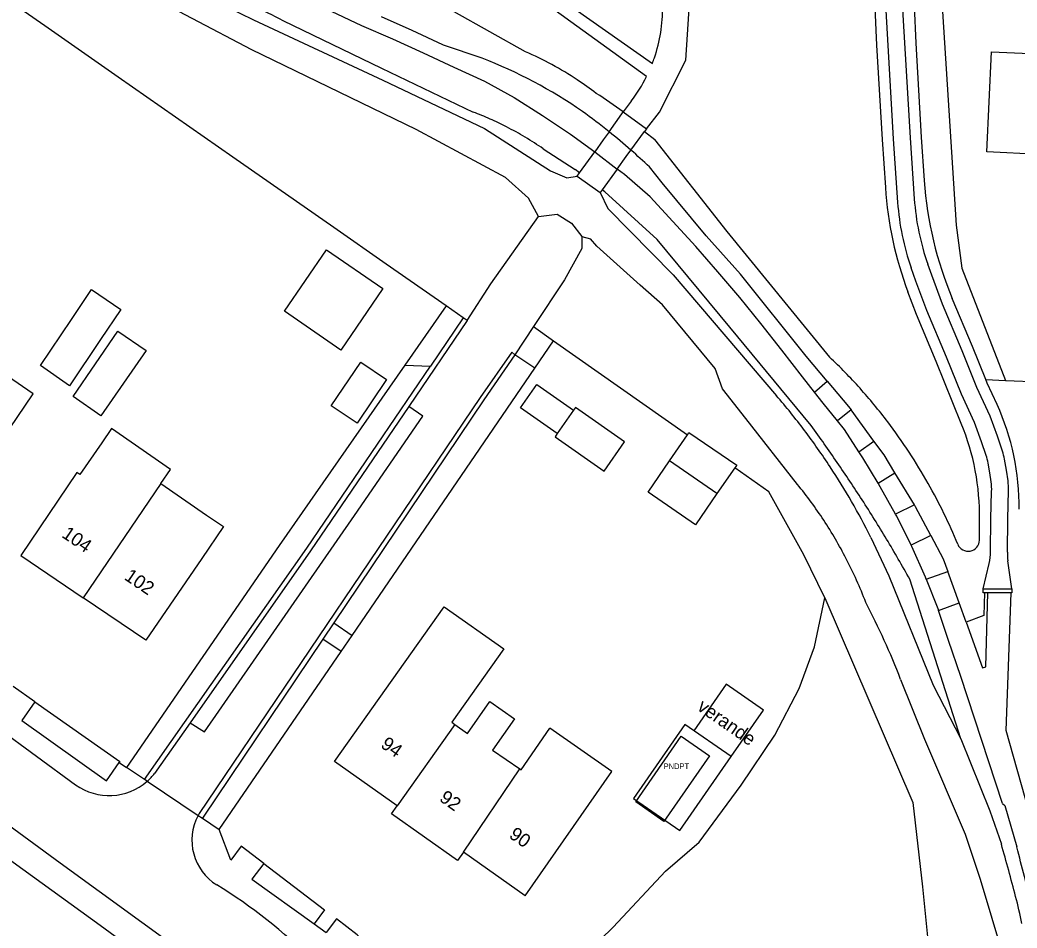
# Model space of a CAD drawing. Extents: x 194485 to 197793, y 468269 to 470822.
# Drawn here: x 194697.5 to 194786.2, y 470533.9 to 470614.7 of the extents above; entities that cross this region are included whole.
import ezdxf

# ---------------------------------------------------------------- set-up
doc = ezdxf.new("R2010")
doc.units = 0
for name, color, linetype in [('BAG plantopografie panden grensvlak pand', 7, 'Continuous'), ('BAG plantopografie panden kenmerkpunt', 7, 'Continuous'), ('BAG plantopografie panden lijnelement overig', 7, 'Continuous'), ('BAG plantopografie panden tekst opmerking', 7, 'Continuous'), ('BGT grensvlak begroeid terreindeel', 7, 'Continuous'), ('BGT grensvlak begroeid terreindeel LR', 7, 'Continuous'), ('BGT grensvlak gebouwinstallatie plus 1', 7, 'Continuous'), ('BGT grensvlak onbegroeid terreindeel', 7, 'Continuous'), ('BGT grensvlak overbruggingsdeel plus 1', 7, 'Continuous'), ('BGT grensvlak pand op maaiveld', 7, 'Continuous'), ('BGT grensvlak pand op maaiveld LR', 7, 'Continuous'), ('BGT grensvlak scheiding', 7, 'Continuous'), ('BGT grensvlak waterdeel', 7, 'Continuous'), ('BGT grensvlak waterdeel LR', 7, 'Continuous'), ('BGT grensvlak wegdeel', 7, 'Continuous'), ('BGT lijnelement kunstwerkdeel stuw', 7, 'Continuous'), ('BGT lijnelement scheiding muur', 7, 'Continuous'), ('BGT tekst huisnummerreeks', 7, 'Continuous')]:
    doc.layers.add(name, color=color, linetype=linetype)

msp = doc.modelspace()

# ---------------------------------------------------------------- linework, layer by layer
at = {"layer": 'BAG plantopografie panden grensvlak pand'}
msp.add_lwpolyline([(194752.065, 470545.461), (194756.171, 470542.607), (194760.737, 470549.175), (194756.632, 470552.029), (194752.065, 470545.461)], dxfattribs=at)
at = {"layer": 'BAG plantopografie panden lijnelement overig'}
msp.add_lwpolyline([(194760.737, 470549.175), (194763.612, 470553.31), (194760.301, 470555.612), (194757.426, 470551.477)], dxfattribs=at)
at = {"layer": 'BGT grensvlak begroeid terreindeel'}
for p, q in [((194742.438, 470611.896), (194736.092, 470615.433)), ((194720.86, 470614.685), (194729.643, 470610.445)), ((194729.643, 470610.445), (194737.801, 470606.529)), ((194753.042, 470604.808), (194753.965, 470604.1)), ((194760.396, 470595.903), (194753.965, 470604.1)), ((194744.031, 470603.254), (194746.881, 470601.409)), ((194747.255, 470601.126), (194746.881, 470601.409)), ((194769.505, 470584.721), (194760.396, 470595.903)), ((194782.823, 470568.438), (194782.843, 470570.264)), ((194781.174, 470550.752), (194776.631, 470564.964))]:
    msp.add_line(p, q, dxfattribs=at)
for points in [[(194774.519, 470729.54), (194774.391, 470727.444), (194774.132, 470719.837), (194773.85, 470711.578), (194773.603, 470699.425), (194773.182, 470668.703), (194773.16, 470658.53), (194772.991, 470642.155), (194773.372, 470619.216), (194773.675, 470612.487)], [(194773.675, 470612.487), (194774.165, 470604.078), (194774.457, 470599.806)], [(194767.858, 470578.625), (194760.617, 470587.39), (194754.175, 470595.195), (194749.493, 470599.43), (194749.273, 470599.597)], [(194781.216, 470578.815), (194778.969, 470584.326), (194777.217, 470588.501), (194776.458, 470590.539)], [(194784.39, 470580.515), (194783.528, 470582.416), (194783.402, 470582.723)]]:
    msp.add_lwpolyline(points, dxfattribs=at)
for centre, radius, start, end in [((194770.667, 470714.262), 111.339, 240.32776, 243.4265), ((194730.879, 470585.111), 29.173, 61.50184, 66.65708), ((194730.387, 470584.149), 30.253, 56.58034, 61.55205), ((194730.069, 470583.746), 30.764, 52.62267, 56.50035), ((194725.566, 470572.065), 42.924, 53.41945, 57.31686), ((194727.555, 470579.555), 28.854, 65.9769, 69.2014), ((194727.292, 470578.985), 29.482, 62.80403, 65.95977), ((194727.185, 470578.791), 29.703, 59.12109, 62.7931), ((194727.454, 470579.247), 29.175, 55.37521, 59.11456), ((194807.396, 470602.069), 33.017, 183.93013, 200.4392), ((194736.685, 470550.065), 47.73, 41.9122, 46.55944), ((194737.205, 470550.538), 47.028, 37.18971, 41.9058), ((194764.352, 470571.425), 22.004, 359.3671, 24.40032), ((194659.901, 470499.662), 133.753, 34.46689, 36.18277), ((194736.802, 470550.237), 47.531, 33.2217, 37.185), ((194760.855, 470570.511), 21.989, 359.35714, 22.18867), ((194737.787, 470550.858), 46.367, 29.18285, 33.24673), ((194661.782, 470500.886), 131.509, 32.74596, 34.49137), ((194739.869, 470551.41), 44.283, 22.10416, 29.8728), ((194655.624, 470496.985), 138.799, 31.02582, 32.7253), ((194660.672, 470500.099), 132.868, 29.22157, 30.99674), ((194781.823, 470568.449), 1, 202.10262, 359.35933)]:
    msp.add_arc(centre, radius, start, end, dxfattribs=at)
at = {"layer": 'BGT grensvlak begroeid terreindeel LR'}
msp.add_lwpolyline([(194769.071, 470563.309), (194776.9, 470545.1), (194777.75, 470537.6), (194779, 470525.15), (194779.193, 470512.957)], dxfattribs=at)
at = {"layer": 'BGT grensvlak gebouwinstallatie plus 1'}
for points in [[(194725.171, 470580.391), (194727.801, 470584.288), (194730.1, 470582.736), (194727.47, 470578.839), (194725.171, 470580.391)], [(194745.28, 470577.921), (194741.999, 470580.215), (194743.451, 470582.293), (194746.733, 470579.998)], [(194759.473, 470572.602), (194757.563, 470569.815), (194753.354, 470572.699), (194755.264, 470575.486)]]:
    msp.add_lwpolyline(points, dxfattribs=at)
at = {"layer": 'BGT grensvlak onbegroeid terreindeel'}
for p, q in [((194744.937, 470586.172), (194756.853, 470577.816)), ((194783.402, 470582.723), (194785.14, 470582.646)), ((194785.14, 470582.646), (194808.41, 470581.622)), ((194715.213, 470542.69), (194726.046, 470558.537))]:
    msp.add_line(p, q, dxfattribs=at)
for points in [[(194779.182, 470744.83), (194778.422, 470736.048), (194777.887, 470727.278), (194777.63, 470719.718), (194777.349, 470711.483), (194777.102, 470699.366), (194776.682, 470668.676), (194776.66, 470658.508), (194776.491, 470642.166), (194776.871, 470619.323), (194777.171, 470612.654)], [(194735.382, 470589.272), (194730.058, 470592.989), (194725.394, 470596.246), (194716.413, 470602.517), (194706.217, 470609.637), (194699.697, 470614.19), (194693.091, 470618.802), (194684.78, 470624.865), (194676.675, 470630.888)], [(194779.404, 470617.811), (194780.746, 470596.469), (194781.255, 470592.647), (194785.14, 470582.646)], [(194777.171, 470612.654), (194777.658, 470604.3), (194777.922, 470600.436)], [(194783.402, 470582.723), (194782.203, 470585.663), (194780.415, 470589.926)], [(194731.72, 470584.018), (194720.531, 470567.962), (194706.969, 470548.216)], [(194727.024, 470559.968), (194741.226, 470580.743), (194743.266, 470583.727)], [(194769.071, 470563.309), (194767.214, 470567.138), (194764.106, 470572.729), (194761.066, 470574.861)], [(194739.471, 470520.723), (194745.69, 470529.554), (194750.244, 470534.006), (194754.901, 470538.976), (194757.903, 470541.564), (194761.629, 470546.638), (194764.63, 470551.09), (194766.804, 470555.231), (194768.149, 470558.959), (194769.071, 470563.309)], [(194698.811, 470554.05), (194706.372, 470548.731), (194706.319, 470548.656)], [(194719.183, 470539.657), (194724.578, 470535.534), (194723.658, 470534.305)], [(194733.74, 470527.297), (194733.278, 470527.827), (194727.472, 470533.322), (194725.628, 470534.731), (194724.725, 470533.544)]]:
    msp.add_lwpolyline(points, dxfattribs=at)
msp.add_arc((194810.87, 470602.701), 33.026, 183.93213, 202.75606, dxfattribs=at)
at = {"layer": 'BGT grensvlak overbruggingsdeel plus 1'}
for p, q in [((194751.147, 470606.534), (194753.204, 470605.032)), ((194749.881, 470604.775), (194749.368, 470604.062)), ((194751.833, 470603.137), (194753.042, 470604.808)), ((194753.204, 470605.032), (194753.042, 470604.808)), ((194749.368, 470604.062), (194748.603, 470602.999)), ((194747.255, 470601.126), (194748.603, 470602.999)), ((194750.617, 470601.455), (194751.418, 470602.563)), ((194751.418, 470602.563), (194751.833, 470603.137)), ((194747.043, 470600.832), (194747.255, 470601.126)), ((194747.043, 470600.832), (194749.105, 470599.364)), ((194750.617, 470601.455), (194749.273, 470599.597)), ((194749.273, 470599.597), (194749.105, 470599.364))]:
    msp.add_line(p, q, dxfattribs=at)
msp.add_lwpolyline([(194749.881, 470604.775), (194751.02, 470606.358), (194751.147, 470606.534)], dxfattribs=at)
at = {"layer": 'BGT grensvlak pand op maaiveld'}
for p, q in [((194783.484, 470602.975), (194783.89, 470611.899)), ((194792.365, 470602.548), (194783.484, 470602.975)), ((194699.321, 470583.983), (194702.058, 470588.074)), ((194704.659, 470586.283), (194701.874, 470582.174)), ((194701.874, 470582.174), (194699.321, 470583.983)), ((194746.733, 470579.998), (194745.28, 470577.921)), ((194755.264, 470575.486), (194756.853, 470577.816)), ((194759.473, 470572.602), (194755.264, 470575.486)), ((194761.066, 470574.861), (194759.473, 470572.602)), ((194710.014, 470573.482), (194714.083, 470570.67)), ((194735.89, 470552.23), (194736.167, 470552.034)), ((194742.064, 470548.015), (194744.609, 470551.699)), ((194750.13, 470547.86), (194744.609, 470551.699)), ((194739.502, 470549.762), (194741.932, 470548.105)), ((194741.932, 470548.105), (194742.064, 470548.015)), ((194742.433, 470536.793), (194750.13, 470547.86)), ((194736.921, 470540.672), (194736.401, 470539.936)), ((194742.433, 470536.793), (194736.921, 470540.672))]:
    msp.add_line(p, q, dxfattribs=at)
for points in [[(194783.89, 470611.899), (194788.671, 470611.669), (194788.718, 470612.657), (194792.816, 470612.463), (194792.365, 470602.548)], [(194726.023, 470585.344), (194721.011, 470588.826), (194724.752, 470594.269), (194729.751, 470590.826), (194726.023, 470585.344)], [(194702.058, 470588.074), (194703.837, 470590.744), (194706.453, 470588.946), (194704.659, 470586.283)], [(194704.69, 470579.497), (194702.216, 470581.225), (194706.198, 470587.039), (194708.71, 470585.298), (194704.69, 470579.497)], [(194696.546, 470578.353), (194698.666, 470581.461), (194692.261, 470585.835), (194690.119, 470582.698)], [(194745.28, 470577.921), (194745.084, 470577.64), (194749.451, 470574.587), (194751.261, 470577.176), (194746.894, 470580.229), (194746.733, 470579.998)], [(194710.014, 470573.482), (194710.88, 470574.736), (194705.626, 470578.366), (194704.76, 470577.112)], [(194756.853, 470577.816), (194756.989, 470578.016), (194761.248, 470575.119), (194761.066, 470574.861)], [(194704.76, 470577.112), (194702.807, 470574.275), (194702.552, 470574.453), (194697.556, 470567.068), (194703.116, 470563.301)], [(194714.083, 470570.67), (194715.578, 470569.662), (194713.66, 470566.817)], [(194713.66, 470566.817), (194708.677, 470559.534), (194703.116, 470563.301)], [(194730.584, 470555.986), (194735.207, 470562.516), (194740.512, 470558.76), (194735.89, 470552.23)], [(194731.044, 470544.798), (194725.461, 470548.75), (194730.584, 470555.986)], [(194736.167, 470552.034), (194737.29, 470551.23), (194739.268, 470554.079), (194741.475, 470552.542), (194739.502, 470549.762)], [(194754.751, 470543.419), (194752.264, 470545.147), (194756.284, 470551), (194758.822, 470549.234), (194754.751, 470543.419)], [(194736.401, 470539.936), (194730.537, 470544.082), (194731.044, 470544.798)]]:
    msp.add_lwpolyline(points, dxfattribs=at)
at = {"layer": 'BGT grensvlak pand op maaiveld LR'}
for p, q in [((194710.014, 470573.482), (194703.116, 470563.301)), ((194736.167, 470552.034), (194731.044, 470544.798)), ((194736.921, 470540.672), (194741.932, 470548.105))]:
    msp.add_line(p, q, dxfattribs=at)
at = {"layer": 'BGT grensvlak scheiding'}
for p, q in [((194783.164, 470564.096), (194785.713, 470564.096)), ((194783.581, 470563.741), (194783.285, 470563.741)), ((194785.651, 470563.741), (194783.581, 470563.741))]:
    msp.add_line(p, q, dxfattribs=at)
for points in [[(194783.285, 470563.741), (194783.218, 470561.73), (194781.632, 470561.143)], [(194781.632, 470561.143), (194783.105, 470557.091), (194783.388, 470557.177), (194783.581, 470563.741)], [(194783.285, 470563.741), (194783.164, 470563.741), (194783.164, 470564.096)], [(194785.713, 470564.096), (194785.713, 470563.741), (194785.651, 470563.741)]]:
    msp.add_lwpolyline(points, dxfattribs=at)
at = {"layer": 'BGT grensvlak waterdeel'}
for p, q in [((194748.603, 470602.999), (194750.617, 470601.455)), ((194773.435, 470577.259), (194771.409, 470580.034)), ((194777.046, 470571.58), (194775.311, 470574.427)), ((194783.164, 470564.096), (194783.685, 470566.359)), ((194785.713, 470564.096), (194785.36, 470566.607)), ((194781.016, 470562.848), (194780.004, 470565.65)), ((194781.632, 470561.143), (194781.016, 470562.848)), ((194784.886, 470545.005), (194781.163, 470556.316))]:
    msp.add_line(p, q, dxfattribs=at)
for points in [[(194774.434, 470616.638), (194775.163, 470604.142), (194775.55, 470598.492)], [(194775.934, 470616.694), (194776.66, 470604.237), (194777.032, 470598.798)], [(194725.154, 470615.501), (194727.875, 470614.238), (194730.628, 470613.045), (194733.353, 470611.79), (194736.076, 470610.532), (194738.794, 470609.263), (194741.428, 470607.826), (194743.962, 470606.221), (194746.458, 470604.556), (194748.603, 470602.999)], [(194738.589, 470611.326), (194735.161, 470612.474), (194735.083, 470612.51), (194732.365, 470613.781), (194729.629, 470615.011)], [(194769.285, 470582.58), (194767.402, 470584.8), (194761.588, 470592.118), (194758.505, 470595.505), (194754.615, 470600.238), (194753.477, 470601.647)], [(194768.147, 470581.615), (194767.076, 470582.966), (194765.261, 470585.355), (194763.394, 470587.703), (194761.501, 470590.03), (194759.566, 470592.323), (194757.59, 470594.58), (194755.565, 470596.794), (194753.527, 470598.995), (194751.258, 470600.958), (194750.617, 470601.455)], [(194783.419, 470575.983), (194783.018, 470577.187), (194782.38, 470578.894), (194781.231, 470581.427), (194779.893, 470584.708), (194778.147, 470588.87), (194777.169, 470591.493), (194776.752, 470592.676)], [(194784.876, 470576.355), (194784.432, 470577.686), (194783.767, 470579.467), (194782.609, 470582.02), (194781.279, 470585.281), (194779.542, 470589.422), (194778.579, 470592.005), (194778.234, 470592.982)], [(194769.285, 470582.58), (194771.19, 470580.334), (194771.409, 470580.034)], [(194770.195, 470579.056), (194768.94, 470580.615), (194768.147, 470581.615)], [(194772.101, 470576.284), (194770.821, 470578.279), (194770.195, 470579.056)], [(194775.311, 470574.427), (194774.341, 470576.018), (194773.435, 470577.259)], [(194773.814, 470573.515), (194772.441, 470575.753), (194772.101, 470576.284)], [(194783.866, 470573.621), (194783.752, 470574.418), (194783.596, 470575.286)], [(194785.369, 470573.706), (194785.234, 470574.656), (194785.054, 470575.658)], [(194775.373, 470570.748), (194774.01, 470573.196), (194773.814, 470573.515)], [(194783.812, 470567.425), (194783.844, 470570.322), (194783.914, 470572.771)], [(194785.311, 470567.36), (194785.344, 470570.292), (194785.417, 470572.856)], [(194778.494, 470568.866), (194777.154, 470571.403), (194777.046, 470571.58)], [(194776.749, 470567.999), (194775.469, 470570.575), (194775.373, 470570.748)], [(194778.494, 470568.866), (194779.593, 470566.787), (194780.004, 470565.65)], [(194778.102, 470564.963), (194778.03, 470565.15), (194776.804, 470567.888), (194776.749, 470567.999)], [(194778.102, 470564.963), (194779.114, 470562.353), (194779.172, 470562.181)], [(194789.323, 470536.717), (194788.507, 470539.638), (194787.209, 470544.355), (194785.191, 470551.513), (194785.651, 470563.741)], [(194781.163, 470556.316), (194780.078, 470559.512), (194779.172, 470562.181)], [(194784.886, 470545.005), (194785.096, 470544.839), (194786.148, 470541.14)]]:
    msp.add_lwpolyline(points, dxfattribs=at)
for centre, radius, start, end in [((194722.498, 470570.231), 44.133, 55.4562, 68.61674), ((194710.988, 470556.492), 61.999, 51.14765, 53.89387), ((194710.878, 470556.314), 62.207, 48.82507, 51.17226), ((194711.443, 470556.921), 61.378, 46.77752, 48.84881), ((194797.488, 470599.994), 21.989, 183.91593, 199.43805), ((194799.035, 470600.313), 22.055, 183.93925, 199.41473), ((194778.686, 470574.41), 4.988, 10.11488, 18.38273), ((194780.052, 470574.752), 5.084, 10.26872, 18.38329), ((194778.913, 470572.915), 5.003, 358.35155, 8.11264), ((194780.416, 470573), 5.003, 358.35155, 8.11264), ((194778.791, 470567.483), 5.021, 347.06926, 359.3427), ((194790.248, 470567.303), 4.937, 179.34048, 188.10584), ((194546.797, 470478.218), 247.483, 13.46575, 14.72899)]:
    msp.add_arc(centre, radius, start, end, dxfattribs=at)
at = {"layer": 'BGT grensvlak waterdeel LR'}
for p, q in [((194768.147, 470581.615), (194769.285, 470582.58)), ((194771.409, 470580.034), (194770.195, 470579.056)), ((194772.101, 470576.284), (194773.435, 470577.259)), ((194773.814, 470573.515), (194775.311, 470574.427)), ((194777.046, 470571.58), (194775.373, 470570.748)), ((194778.494, 470568.866), (194776.749, 470567.999)), ((194778.102, 470564.963), (194780.004, 470565.65)), ((194779.172, 470562.181), (194781.016, 470562.848))]:
    msp.add_line(p, q, dxfattribs=at)
at = {"layer": 'BGT grensvlak wegdeel'}
for p, q in [((194737.372, 470622.383), (194753.732, 470610.859)), ((194753.216, 470609.687), (194736.912, 470621.494)), ((194751.853, 470607.5), (194751.147, 470606.534)), ((194747.456, 470595.447), (194748.218, 470595.24)), ((194735.382, 470589.272), (194731.72, 470584.018)), ((194736.907, 470588.206), (194735.382, 470589.272)), ((194737.248, 470587.967), (194732.065, 470580.333)), ((194736.907, 470588.206), (194734.002, 470583.927)), ((194737.248, 470587.967), (194736.907, 470588.206)), ((194743.173, 470587.441), (194741.515, 470584.924)), ((194743.173, 470587.441), (194744.937, 470586.172)), ((194741.515, 470584.924), (194738.733, 470580.924)), ((194743.266, 470583.727), (194741.515, 470584.924)), ((194731.72, 470584.018), (194734.002, 470583.927)), ((194738.733, 470580.924), (194725.395, 470561.082)), ((194725.395, 470561.082), (194724.428, 470559.643)), ((194725.395, 470561.082), (194727.024, 470559.968)), ((194726.046, 470558.537), (194727.024, 470559.968)), ((194726.046, 470558.537), (194724.428, 470559.643)), ((194698.811, 470554.05), (194696.889, 470555.403)), ((194692.056, 470554.269), (194702.437, 470546.679)), ((194698.811, 470554.05), (194697.662, 470552.384)), ((194697.662, 470552.384), (194705.184, 470547.031)), ((194712.626, 470552.199), (194709.46, 470547.684)), ((194701.055, 470539.687), (194688.113, 470549.192)), ((194705.184, 470547.031), (194706.319, 470548.656)), ((194706.319, 470548.656), (194706.969, 470548.216)), ((194708.566, 470547.134), (194706.969, 470548.216)), ((194708.793, 470546.981), (194708.566, 470547.134)), ((194708.793, 470546.981), (194713.336, 470543.944)), ((194713.336, 470543.944), (194713.71, 470543.694)), ((194713.71, 470543.694), (194715.213, 470542.69)), ((194712.769, 470531.198), (194701.055, 470539.687)), ((194723.658, 470534.305), (194724.725, 470533.544))]:
    msp.add_line(p, q, dxfattribs=at)
for points in [[(194743.606, 470597.23), (194742.708, 470598.874), (194740.675, 470600.692), (194732.734, 470604.967), (194718.113, 470612.063), (194707.503, 470617.66)], [(194753.204, 470605.032), (194754.361, 470606.531), (194756.722, 470611.134), (194757.073, 470616.663)], [(194718.26, 470614.724), (194729.755, 470609.361), (194738.809, 470605.065), (194744.667, 470601.292), (194746.128, 470600.676), (194747.043, 470600.832)], [(194749.105, 470599.364), (194749.785, 470597.944), (194755.579, 470592.036), (194764.776, 470581.293)], [(194737.248, 470587.967), (194739.358, 470591.249), (194743.606, 470597.23)], [(194743.606, 470597.23), (194745.273, 470597.439), (194746.555, 470596.652), (194747.456, 470595.447)], [(194747.456, 470595.447), (194747.454, 470594.387), (194745.92, 470591.613), (194743.173, 470587.441)], [(194766.643, 470573.394), (194762.062, 470579.252), (194759.964, 470581.9), (194759.312, 470583.718), (194754.626, 470589.381), (194752.66, 470591.14), (194748.799, 470594.608), (194748.218, 470595.24)], [(194743.266, 470583.727), (194743.279, 470583.747), (194744.937, 470586.172)], [(194741.515, 470584.924), (194741.23, 470585.15), (194738.411, 470581.14)], [(194708.566, 470547.134), (194722.994, 470567.711), (194734.002, 470583.927)], [(194738.411, 470581.14), (194713.43, 470544.111), (194713.336, 470543.944)], [(194712.626, 470552.199), (194713.888, 470551.377), (194727.225, 470570.639), (194733.33, 470579.457), (194732.065, 470580.333)], [(194732.065, 470580.333), (194723.339, 470567.478), (194712.626, 470552.199)], [(194773.178, 470568.686), (194774.762, 470565.254), (194778.702, 470555.537), (194781.174, 470550.752)], [(194724.428, 470559.643), (194713.778, 470543.8), (194713.71, 470543.694)], [(194775.818, 470556.047), (194777.936, 470550.742), (194781.571, 470542.269), (194782.878, 470538.288), (194784.957, 470531.327)], [(194781.174, 470550.752), (194783.747, 470544.341), (194784.777, 470541.377)], [(194726.856, 470506.908), (194725.926, 470510.681), (194724.606, 470514.488), (194722.368, 470518.679), (194720.579, 470520.944), (194717.885, 470524.062), (194715.614, 470526.084), (194704.608, 470534.155), (194684.263, 470548.857)], [(194719.183, 470539.657), (194717.156, 470541.206), (194716.226, 470539.966), (194715.213, 470542.69)], [(194719.183, 470539.657), (194718.1, 470538.273), (194723.658, 470534.305)]]:
    msp.add_lwpolyline(points, dxfattribs=at)
for centre, radius, start, end in [((194760.879, 470701.076), 96.297, 239.39564, 243.73118), ((194741.028, 470615.774), 13.621, 350.81545, 0.55063), ((194741.149, 470615.735), 13.495, 341.06791, 350.89567), ((194742.111, 470615.388), 12.473, 338.70665, 341.14249), ((194740.931, 470615.825), 13.733, 322.68422, 333.45114), ((194717.078, 470540.369), 62.848, 37.01123, 40.62866), ((194717.087, 470540.405), 62.819, 33.37038, 36.98985), ((194717.78, 470540.851), 61.995, 30.02849, 33.37912), ((194737.645, 470549.657), 37.475, 33.25422, 39.30331), ((194717.124, 470540.443), 62.768, 26.74122, 30.05083), ((194737.678, 470549.637), 37.458, 27.25458, 33.30627), ((194736.982, 470549.281), 38.239, 20.85585, 27.25185), ((194713.712, 470532.041), 66.584, 21.13327, 27.60578), ((194705.373, 470550.894), 5.197, 311.15525, 321.85523), ((194705.424, 470550.847), 5.128, 234.37413, 311.0665), ((194717.44, 470541.73), 4.663, 151.65641, 238.34826), ((194597.725, 470487.719), 194.596, 14.58758, 16.0061), ((194691.304, 470498.999), 45.428, 44.8519, 58.56908), ((194734.586, 470523.379), 53.165, 11.8843, 14.54356)]:
    msp.add_arc(centre, radius, start, end, dxfattribs=at)
at = {"layer": 'BGT lijnelement kunstwerkdeel stuw'}
for p, q in [((194768.147, 470581.615), (194769.285, 470582.58)), ((194771.409, 470580.034), (194770.195, 470579.056)), ((194772.101, 470576.284), (194773.435, 470577.259)), ((194773.814, 470573.515), (194775.311, 470574.427)), ((194777.046, 470571.58), (194775.373, 470570.748)), ((194778.494, 470568.866), (194776.749, 470567.999)), ((194778.102, 470564.963), (194780.004, 470565.65)), ((194779.172, 470562.181), (194781.016, 470562.848))]:
    msp.add_line(p, q, dxfattribs=at)
at = {"layer": 'BGT lijnelement scheiding muur'}
msp.add_line((194784.886, 470545.005), (194781.163, 470556.316), dxfattribs=at)

# ---------------------------------------------------------------- texts
at = {"layer": 'BAG plantopografie panden kenmerkpunt'}
msp.add_text('PNDPT', height=0.5, dxfattribs=at).set_placement((194754.737, 470548.07))
at = {"layer": 'BAG plantopografie panden tekst opmerking'}
msp.add_text('verande', height=1.2, rotation=325.18635, dxfattribs=at).set_placement((194757.637, 470553.391))
at = {"layer": 'BGT tekst huisnummerreeks'}
for s, rotation, p in [('104', 325.9, (194701.12, 470568.76)), ('102', 325.9, (194706.683, 470564.991)), ('94', 324.7, (194729.49, 470550.064)), ('92', 324.7, (194734.707, 470545.298)), ('90', 324.9, (194740.904, 470542.026))]:
    msp.add_text(s, height=1.2, rotation=rotation, dxfattribs=at).set_placement(p)

doc.saveas('drawing.dxf')
